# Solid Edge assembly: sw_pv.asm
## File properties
Author: Sham
Template: Sync Iso Assembly.asm
Last saved by: CADCIM
Revision: 5
Application: Solid Edge
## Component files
base.par
Screw.par
moveable jaw.par
handle.par
handle screw.par
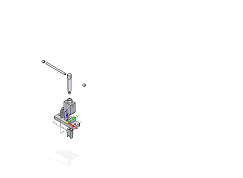
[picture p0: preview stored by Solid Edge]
